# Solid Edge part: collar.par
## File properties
Title: Collar
Author: Abhinav Rai
Template: Normal.par
Last saved by: Cadcim
Revision: 7
Application: Solid Edge
Density: 0.0000078 kg/mm^3
Accuracy: 0.01
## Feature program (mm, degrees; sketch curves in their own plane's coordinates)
sketch for "unnamed RevolvedProtrusion 1" plane through (0, 0, 0) normal (0, -1, 0) x-axis (1, 0, 0)
  line (6.5405, -15.9527) -> (9.1186, -15.9527)
  line (9.1186, -15.9527) -> (9.1186, -36.5775)
  line (9.1186, -36.5775) -> (6.5405, -36.5775)
  line (6.5405, -15.9527) -> (6.5405, -36.5775)
revolve "unnamed RevolvedProtrusion 1" add finite 360 deg
sketch for "unnamed Cutout 1" plane through (0, 0, 0) normal (0, -1, 0) x-axis (1, 0, 0)
  line (-1.1811, -15.9527) -> (1.1811, -15.9527)
  line (1.1811, -15.9527) -> (1.1811, -19.1277)
  line (1.1811, -19.1277) -> (-1.1811, -19.1277)
  line (-1.1811, -19.1277) -> (-1.1811, -15.9527)
extrude "unnamed Cutout 1" cut finite 50.8 symmetric
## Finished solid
Body 1: solid body, 11 faces, 26 edges, 16 vertices.
  Faces by surface: plane 9, cylinder 2
  Edges by curve: line 16, circle 10
Bounding box of the edges (mm): 18.237 x 18.237 x 20.625, from (-9.1186, -9.1186, -36.5775) to (9.1186, 9.1186, -15.9527).
Cylindrical faces by radius (mm): R6.5405 x1, R9.1186 x1
Planar faces by outward normal: +x 2, +z 4, -x 2, -z 1
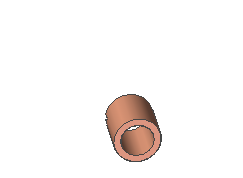
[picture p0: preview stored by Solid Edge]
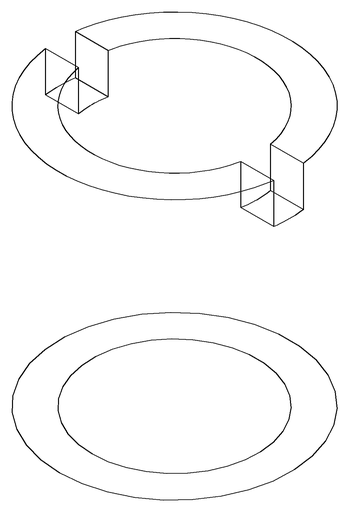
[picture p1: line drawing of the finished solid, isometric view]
